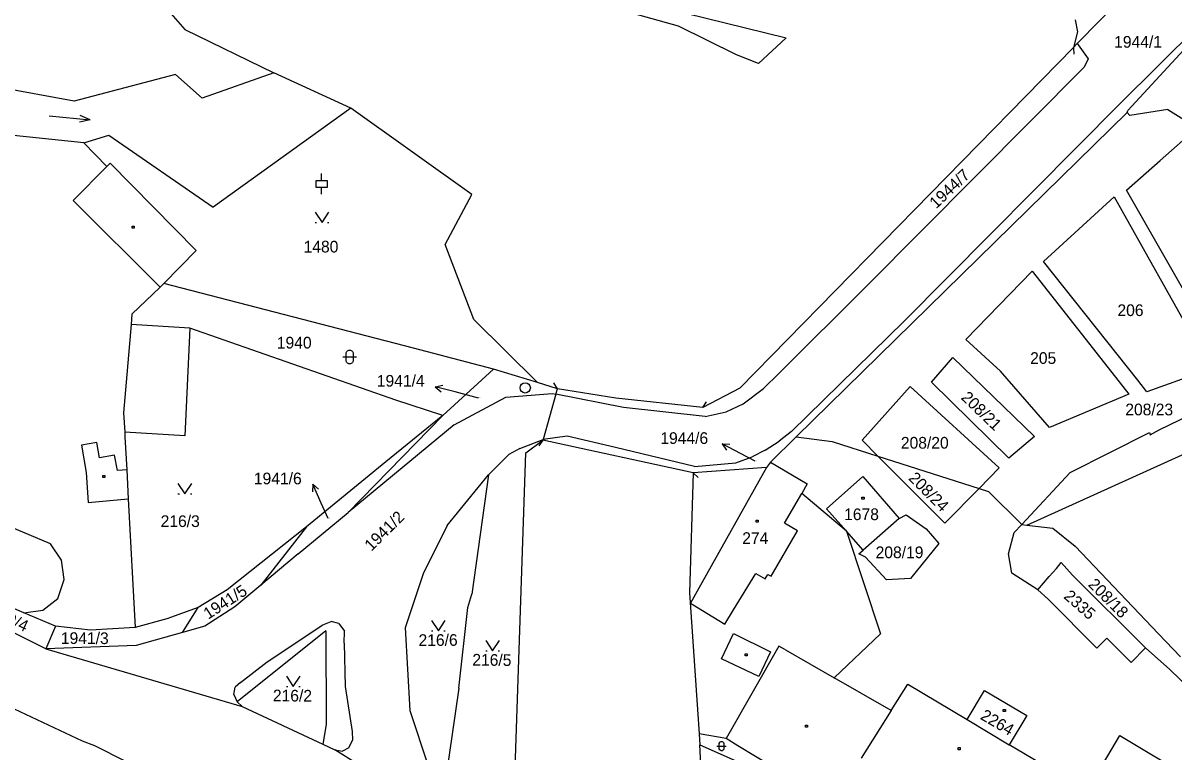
# Model space of a CAD drawing. Extents: x -795483 to -789093, y -1112258 to -1108741.
# Drawn here: x -791907.6 to -791740.2, y -1110894.1 to -1110788.1 of the extents above; entities that cross this region are included whole.
import ezdxf

# ---------------------------------------------------------------- set-up
doc = ezdxf.new("R2010")
doc.units = 0
for name, color, linetype in [('Komunikace', 7, 'Continuous'), ('Popis vodovodních řadů', 7, 'Continuous'), ('Vrstva 1', 7, 'Continuous'), ('Vrstva 14', 7, 'Continuous'), ('Vrstva 15', 7, 'Continuous'), ('Vrstva 16', 7, 'Continuous'), ('Vrstva 2', 7, 'Continuous'), ('Vrstva 23', 7, 'Continuous'), ('Vrstva 25', 7, 'Continuous'), ('Vrstva 28', 7, 'Continuous')]:
    doc.layers.add(name, color=color, linetype=linetype)

msp = doc.modelspace()

# ---------------------------------------------------------------- linework, layer by layer
at = {"layer": 'Komunikace'}
for p, q in [((-791841.35, -1110842.63), (-791844.74, -1110841.73)), ((-791801.13, -1110851.81), (-791803.27, -1110850.69)), ((-791863.23, -1110860.11), (-791864.23, -1110857.89))]:
    msp.add_line(p, q, dxfattribs=at)
at = {"layer": 'Popis vodovodních řadů'}
for p, q in [((-791754.82, -1110791.63), (-791754.78, -1110792.62)), ((-791829.89, -1110841.26), (-791830.39, -1110840.41)), ((-791808.75, -1110843.97), (-791808.2, -1110843.15)), ((-791832, -1110848.76), (-791832.56, -1110849.57)), ((-791810.14, -1110853.5), (-791809.42, -1110854.18))]:
    msp.add_line(p, q, dxfattribs=at)
at = {"layer": 'Vrstva 1'}
for p, q in [((-791894.38, -1110777.13), (-791884.07, -1110789.01)), ((-791812.29, -1110788.52), (-791844.01, -1110779.66)), ((-791746.48, -1110783.12), (-791754.27, -1110791.07)), ((-791814.17, -1110785.93), (-791796.61, -1110790.22)), ((-791803.83, -1110792.73), (-791812.29, -1110788.52)), ((-791754.6, -1110787.64), (-791754.26, -1110789.34)), ((-791736.77, -1110788.62), (-791748.11, -1110799.81)), ((-791884.07, -1110789.01), (-791871.1, -1110795.31)), ((-791796.61, -1110790.22), (-791800.63, -1110793.96)), ((-791754.26, -1110789.34), (-791754.82, -1110791.63)), ((-791736.2, -1110789.15), (-791746.92, -1110800.79)), ((-791803.36, -1110841.2), (-791754.82, -1110791.63)), ((-791754.27, -1110791.07), (-791754.82, -1110791.63)), ((-791754.27, -1110791.07), (-791754.16, -1110791.23)), ((-791754.16, -1110791.23), (-791752.67, -1110793.3)), ((-791800.63, -1110793.96), (-791803.83, -1110792.73)), ((-791752.67, -1110793.3), (-791753.29, -1110794.5)), ((-791871.1, -1110795.31), (-791881.53, -1110798.99)), ((-791859.93, -1110800.45), (-791871.1, -1110795.31)), ((-791753.29, -1110794.5), (-791784.85, -1110826.24)), ((-791900.14, -1110799.45), (-791917.76, -1110796.23)), ((-791885.41, -1110795.57), (-791900.14, -1110799.45)), ((-791881.53, -1110798.99), (-791885.41, -1110795.57)), ((-791779.43, -1110831.43), (-791748.11, -1110799.81)), ((-791859.93, -1110800.45), (-791879.96, -1110814.85)), ((-791842.32, -1110813.02), (-791859.93, -1110800.45)), ((-791795.15, -1110848.25), (-791747.03, -1110801.1)), ((-791747.03, -1110801.1), (-791746.92, -1110800.79)), ((-791746.61, -1110801.53), (-791747.03, -1110801.1)), ((-791741.11, -1110800.67), (-791746.61, -1110801.53)), ((-791741.11, -1110800.67), (-791736.82, -1110803.3)), ((-791742.21, -1110808.05), (-791736.82, -1110803.3)), ((-791898.73, -1110805.48), (-791911.39, -1110804.2)), ((-791898.73, -1110805.48), (-791895.11, -1110804.41)), ((-791895.11, -1110804.41), (-791879.96, -1110814.85)), ((-791895.41, -1110808.96), (-791898.73, -1110805.48)), ((-791894.93, -1110808.48), (-791895.41, -1110808.96)), ((-791882.39, -1110821.16), (-791894.93, -1110808.48)), ((-791747.14, -1110812.4), (-791742.21, -1110808.05)), ((-791846.18, -1110820.3), (-791842.32, -1110813.02)), ((-791759.17, -1110822.74), (-791748.93, -1110813.36)), ((-791748.93, -1110813.36), (-791736.01, -1110836.4)), ((-791733.92, -1110835.51), (-791747.14, -1110812.4)), ((-791842.01, -1110831.17), (-791846.18, -1110820.3)), ((-791887.14, -1110825.95), (-791882.39, -1110821.16)), ((-791745.49, -1110840), (-791759.17, -1110822.74)), ((-791770.5, -1110834.09), (-791760.84, -1110824.16)), ((-791760.84, -1110824.16), (-791747.66, -1110840.95)), ((-791887.66, -1110826.48), (-791891.77, -1110830.43)), ((-791887.14, -1110825.95), (-791887.66, -1110826.48)), ((-791850.81, -1110835.35), (-791887.14, -1110825.95)), ((-791784.85, -1110826.24), (-791797.61, -1110838.98)), ((-791891.77, -1110830.43), (-791891.89, -1110831.92)), ((-791891.89, -1110831.92), (-791892.96, -1110844.76)), ((-791883.33, -1110832.43), (-791891.89, -1110831.92)), ((-791832.79, -1110840.36), (-791842.01, -1110831.17)), ((-791779.43, -1110831.43), (-791795.84, -1110847.47)), ((-791853.37, -1110842.93), (-791883.33, -1110832.43)), ((-791839.15, -1110838.41), (-791850.81, -1110835.35)), ((-791770.5, -1110834.09), (-791765.43, -1110838.69)), ((-791775.47, -1110840.31), (-791772.39, -1110836.7)), ((-791772.39, -1110836.7), (-791760.48, -1110848.22)), ((-791839.15, -1110838.41), (-791846.52, -1110845.16)), ((-791832.79, -1110840.36), (-791839.15, -1110838.41)), ((-791758.33, -1110846.89), (-791765.43, -1110838.69)), ((-791734.89, -1110838.4), (-791744.14, -1110841.69)), ((-791829.89, -1110841.26), (-791832.79, -1110840.36)), ((-791799.91, -1110841.24), (-791797.61, -1110838.98)), ((-791764.23, -1110851.35), (-791775.47, -1110840.31)), ((-791761.62, -1110861.08), (-791714.24, -1110839.64)), ((-791744.14, -1110841.69), (-791745.49, -1110840)), ((-791837.38, -1110842.51), (-791830.66, -1110841.96)), ((-791830.12, -1110842.07), (-791831.97, -1110848.65)), ((-791830.66, -1110841.96), (-791830.12, -1110842.07)), ((-791830.12, -1110842.07), (-791829.89, -1110841.26)), ((-791820.27, -1110843.98), (-791830.12, -1110842.07)), ((-791821.37, -1110842.61), (-791829.89, -1110841.26)), ((-791803.36, -1110841.2), (-791808.75, -1110843.97)), ((-791802.88, -1110843.44), (-791799.91, -1110841.24)), ((-791785.57, -1110848.76), (-791778.6, -1110840.95)), ((-791778.6, -1110840.95), (-791765.62, -1110852.78)), ((-791746.8, -1110842.05), (-791758.33, -1110846.89)), ((-791747.66, -1110840.95), (-791746.8, -1110842.05)), ((-791846.52, -1110845.16), (-791853.37, -1110842.93)), ((-791844.89, -1110846.53), (-791837.38, -1110842.51)), ((-791808.75, -1110843.97), (-791821.37, -1110842.61)), ((-791805.32, -1110844.61), (-791802.88, -1110843.44)), ((-791742.35, -1110847.24), (-791732.22, -1110842.34)), ((-791892.96, -1110844.76), (-791892.81, -1110847.56)), ((-791860.31, -1110859.26), (-791846.52, -1110845.16)), ((-791846.52, -1110845.16), (-791854.85, -1110851.89)), ((-791808.39, -1110845.32), (-791820.27, -1110843.98)), ((-791808.39, -1110845.32), (-791805.32, -1110844.61)), ((-791844.89, -1110846.53), (-791860.31, -1110859.26)), ((-791892.81, -1110847.56), (-791892.77, -1110848.26)), ((-791892.77, -1110848.26), (-791892.51, -1110853.06)), ((-791835.35, -1110849.94), (-791831.97, -1110848.65)), ((-791834.48, -1110850.6), (-791832, -1110848.76)), ((-791832, -1110848.76), (-791831.97, -1110848.65)), ((-791810.14, -1110853.5), (-791832, -1110848.76)), ((-791828.44, -1110848.15), (-791831.97, -1110848.65)), ((-791821.41, -1110849.79), (-791828.44, -1110848.15)), ((-791799.66, -1110850.18), (-791797.61, -1110848.87)), ((-791798.91, -1110851.94), (-791795.15, -1110848.25)), ((-791795.84, -1110847.47), (-791797.61, -1110848.87)), ((-791795.15, -1110848.25), (-791789.91, -1110848.95)), ((-791785.57, -1110848.76), (-791783.27, -1110851.07)), ((-791760.48, -1110848.22), (-791764.23, -1110851.35)), ((-791755.33, -1110853.44), (-791743.79, -1110847.64)), ((-791743.79, -1110847.64), (-791743.67, -1110847.95)), ((-791743.67, -1110847.95), (-791742.35, -1110847.24)), ((-791835.35, -1110849.94), (-791836.94, -1110850.83)), ((-791809.96, -1110852.58), (-791821.41, -1110849.79)), ((-791799.66, -1110850.18), (-791801.56, -1110851.15)), ((-791789.91, -1110848.95), (-791783.27, -1110851.07)), ((-791854.85, -1110851.89), (-791866.37, -1110861.35)), ((-791836.94, -1110850.83), (-791839.92, -1110853.77)), ((-791836.18, -1110901.7), (-791834.48, -1110850.6)), ((-791809.96, -1110852.58), (-791803.92, -1110852.02)), ((-791803.92, -1110852.02), (-791801.56, -1110851.15)), ((-791798.91, -1110851.94), (-791799.46, -1110852.71)), ((-791798.91, -1110851.94), (-791793.54, -1110855.1)), ((-791773.53, -1110860.81), (-791783.27, -1110851.07)), ((-791783.27, -1110851.07), (-791768.55, -1110855.76)), ((-791892.51, -1110853.06), (-791892.29, -1110857.28)), ((-791845.91, -1110861.16), (-791839.92, -1110853.77)), ((-791839.92, -1110853.77), (-791842.33, -1110871.11)), ((-791810.14, -1110853.5), (-791810.69, -1110870.94)), ((-791799.46, -1110852.71), (-791810.14, -1110853.5)), ((-791765.62, -1110852.78), (-791768.55, -1110855.76)), ((-791762.35, -1110860.99), (-791755.33, -1110853.44)), ((-791793.54, -1110855.1), (-791794.34, -1110856.5)), ((-791790.74, -1110858.73), (-791785.47, -1110854.03)), ((-791785.47, -1110854.03), (-791780.16, -1110860.15)), ((-791787.85, -1110861.97), (-791794.34, -1110856.5)), ((-791773.53, -1110860.81), (-791768.55, -1110855.76)), ((-791768.55, -1110855.76), (-791767.2, -1110856.19)), ((-791767.2, -1110856.19), (-791762.35, -1110860.99)), ((-791892.29, -1110857.28), (-791891.28, -1110876)), ((-791787.85, -1110861.97), (-791790.74, -1110858.73)), ((-791907.46, -1110873.84), (-791939.94, -1110860.09)), ((-791867.6, -1110865.28), (-791860.31, -1110859.26)), ((-791780.16, -1110860.15), (-791785.4, -1110864.72)), ((-791780.16, -1110860.15), (-791779.18, -1110859.58)), ((-791779.18, -1110859.58), (-791776.26, -1110861.61)), ((-791866.37, -1110861.35), (-791877.91, -1110870.49)), ((-791866.37, -1110861.35), (-791872.99, -1110869.81)), ((-791845.91, -1110861.16), (-791849.39, -1110868.16)), ((-791787.85, -1110861.97), (-791782.9, -1110876.92)), ((-791785.4, -1110864.72), (-791787.85, -1110861.97)), ((-791776.26, -1110861.61), (-791774.41, -1110863.75)), ((-791764.26, -1110865.28), (-791763.43, -1110862.15)), ((-791763.43, -1110862.15), (-791762.35, -1110860.99)), ((-791762.35, -1110860.99), (-791761.62, -1110861.08)), ((-791761.62, -1110861.08), (-791757.81, -1110861.54)), ((-791757.81, -1110861.54), (-791754.58, -1110864.14)), ((-791774.41, -1110863.75), (-791778.51, -1110868.84)), ((-791867.6, -1110865.28), (-791872.99, -1110869.81)), ((-791786.03, -1110865.27), (-791785.4, -1110864.72)), ((-791785.05, -1110865.75), (-791786.03, -1110865.27)), ((-791763.77, -1110868.09), (-791764.26, -1110865.28)), ((-791754.58, -1110864.14), (-791742.48, -1110876.91)), ((-791782.03, -1110869.05), (-791785.05, -1110865.75)), ((-791757.32, -1110867.39), (-791756.61, -1110866.53)), ((-791756.61, -1110866.53), (-791754.97, -1110868.38)), ((-791849.39, -1110868.16), (-791852.01, -1110876.03)), ((-791778.51, -1110868.84), (-791782.03, -1110869.05)), ((-791760, -1110870.51), (-791763.77, -1110868.09)), ((-791760, -1110870.51), (-791758.34, -1110868.57)), ((-791758.34, -1110868.57), (-791757.32, -1110867.39)), ((-791744.33, -1110878.96), (-791754.97, -1110868.38)), ((-791877.91, -1110870.49), (-791882.12, -1110873.06)), ((-791872.99, -1110869.81), (-791876.77, -1110872.98)), ((-791758.53, -1110871.87), (-791760, -1110870.51)), ((-791842.9, -1110873.09), (-791842.33, -1110871.11)), ((-791810.69, -1110870.94), (-791809.26, -1110891.45)), ((-791751.45, -1110879), (-791758.53, -1110871.87)), ((-791902.87, -1110875.81), (-791907.46, -1110873.84)), ((-791882.12, -1110873.06), (-791886.7, -1110874.73)), ((-791884.4, -1110876.7), (-791882.12, -1110873.06)), ((-791876.77, -1110872.98), (-791881.13, -1110875.77)), ((-791844.2, -1110884.82), (-791842.9, -1110873.09)), ((-791886.7, -1110874.73), (-791891.28, -1110876)), ((-791898.93, -1110892.51), (-791934.57, -1110875.82)), ((-791904.28, -1110879.09), (-791908.73, -1110876.84)), ((-791902.87, -1110875.81), (-791904.28, -1110879.09)), ((-791897.79, -1110876.36), (-791902.87, -1110875.81)), ((-791891.28, -1110876), (-791897.79, -1110876.36)), ((-791884.4, -1110876.7), (-791891.14, -1110878.62)), ((-791881.13, -1110875.77), (-791884.4, -1110876.7)), ((-791863.57, -1110876.49), (-791876.47, -1110886.81)), ((-791863.57, -1110876.49), (-791863.52, -1110890.07)), ((-791852.01, -1110876.03), (-791851.35, -1110888.05)), ((-791782.9, -1110876.92), (-791789.61, -1110883.31)), ((-791742.48, -1110876.91), (-791739.28, -1110880.24)), ((-791891.14, -1110878.62), (-791904.28, -1110879.09)), ((-791797.68, -1110878.7), (-791805.34, -1110892.14)), ((-791796.71, -1110879.25), (-791797.68, -1110878.7)), ((-791750, -1110877.55), (-791751.45, -1110879)), ((-791746.45, -1110881.09), (-791750, -1110877.55)), ((-791744.33, -1110878.96), (-791746.45, -1110881.09)), ((-791740.83, -1110882.08), (-791744.33, -1110878.96)), ((-791904.28, -1110879.09), (-791875.7, -1110887.48)), ((-791796.71, -1110879.25), (-791789.61, -1110883.31)), ((-791730.17, -1110892.47), (-791740.83, -1110882.08)), ((-791781.33, -1110888.04), (-791789.61, -1110883.31)), ((-791844.2, -1110884.82), (-791846.39, -1110899.61)), ((-791781.33, -1110888.04), (-791778.93, -1110884.24)), ((-791778.93, -1110884.24), (-791770.29, -1110889.37)), ((-791770.29, -1110889.37), (-791767.78, -1110885.14)), ((-791767.78, -1110885.14), (-791761.63, -1110888.77)), ((-791875.7, -1110887.48), (-791876.47, -1110886.81)), ((-791875.7, -1110887.48), (-791864, -1110892.94)), ((-791851.35, -1110888.05), (-791848.69, -1110896.1)), ((-791761.63, -1110888.77), (-791764.16, -1110893.02)), ((-791863.52, -1110890.07), (-791864, -1110892.94)), ((-791770.29, -1110889.37), (-791764.16, -1110893.02)), ((-791805.34, -1110892.14), (-791809.26, -1110891.45)), ((-791809.26, -1110891.45), (-791809.18, -1110893.03)), ((-791803.63, -1110893.17), (-791805.34, -1110892.14)), ((-791753.02, -1110899.97), (-791748.09, -1110891.69)), ((-791748.09, -1110891.69), (-791718.22, -1110909.47)), ((-791897.16, -1110893.17), (-791898.93, -1110892.51)), ((-791892.66, -1110895.47), (-791897.16, -1110893.17)), ((-791864, -1110892.94), (-791862.24, -1110893.76)), ((-791839.67, -1110907.9), (-791862.24, -1110893.76)), ((-791809.18, -1110893.03), (-791789.18, -1110901.88)), ((-791808.61, -1110904.53), (-791809.18, -1110893.03)), ((-791789.18, -1110901.88), (-791803.63, -1110893.17)), ((-791756.21, -1110897.75), (-791764.16, -1110893.02))]:
    msp.add_line(p, q, dxfattribs=at)
at = {"layer": 'Vrstva 16'}
for p, q in [((-791847.64, -1110840.96), (-791846.54, -1110840.73)), ((-791844.74, -1110841.73), (-791847.64, -1110840.96)), ((-791847.64, -1110840.96), (-791846.8, -1110841.7)), ((-791803.27, -1110850.69), (-791805.93, -1110849.29)), ((-791805.93, -1110849.29), (-791805.27, -1110850.2)), ((-791805.93, -1110849.29), (-791804.81, -1110849.32)), ((-791865.47, -1110855.16), (-791865.51, -1110856.27)), ((-791864.23, -1110857.89), (-791865.47, -1110855.16)), ((-791865.47, -1110855.16), (-791864.6, -1110855.86))]:
    msp.add_line(p, q, dxfattribs=at)
at = {"layer": 'Vrstva 2'}
for p, q in [((-791895.41, -1110808.96), (-791900.29, -1110813.87)), ((-791900.29, -1110813.87), (-791887.66, -1110826.48)), ((-791883.33, -1110832.43), (-791884.06, -1110848.13)), ((-791884.06, -1110848.13), (-791892.81, -1110847.56)), ((-791896.88, -1110849.07), (-791899.08, -1110849.47)), ((-791899.08, -1110849.47), (-791898.42, -1110853.44)), ((-791896.47, -1110851.31), (-791896.88, -1110849.07)), ((-791894.28, -1110850.91), (-791896.47, -1110851.31)), ((-791893.86, -1110853.13), (-791894.28, -1110850.91)), ((-791898.42, -1110853.44), (-791898.1, -1110857.79)), ((-791892.51, -1110853.06), (-791893.86, -1110853.13)), ((-791799.46, -1110852.71), (-791809.33, -1110870.27)), ((-791903.61, -1110863.83), (-791924.1, -1110855.18)), ((-791796.83, -1110860.82), (-791794.34, -1110856.5)), ((-791898.1, -1110857.79), (-791892.29, -1110857.28)), ((-791798.81, -1110868.53), (-791794.97, -1110861.9)), ((-791794.97, -1110861.9), (-791796.83, -1110860.82)), ((-791902.02, -1110866.18), (-791903.61, -1110863.83)), ((-791901.61, -1110868.99), (-791902.02, -1110866.18)), ((-791804.25, -1110873.41), (-791801.03, -1110868.12)), ((-791801.03, -1110868.12), (-791799.66, -1110868.92)), ((-791799.66, -1110868.92), (-791799.28, -1110868.26)), ((-791799.28, -1110868.26), (-791798.81, -1110868.53)), ((-791902.55, -1110871.74), (-791901.61, -1110868.99)), ((-791809.33, -1110870.27), (-791810.53, -1110872.42)), ((-791904.7, -1110873.47), (-791902.55, -1110871.74)), ((-791907.46, -1110873.84), (-791904.7, -1110873.47)), ((-791810.53, -1110872.42), (-791805.53, -1110875.51)), ((-791805.53, -1110875.51), (-791804.25, -1110873.41)), ((-791872.09, -1110880.95), (-791864, -1110875.58)), ((-791864, -1110875.58), (-791862.8, -1110875.1)), ((-791861.66, -1110875.41), (-791862.8, -1110875.1)), ((-791861.66, -1110875.41), (-791860.83, -1110876.52)), ((-791860.89, -1110878.24), (-791860.83, -1110876.52)), ((-791806, -1110880.53), (-791804.28, -1110876.86)), ((-791804.28, -1110876.86), (-791798.9, -1110879.51)), ((-791860.89, -1110878.24), (-791860.74, -1110884.58)), ((-791800.61, -1110883.1), (-791806, -1110880.53)), ((-791798.9, -1110879.51), (-791800.61, -1110883.1)), ((-791875.98, -1110883.97), (-791872.09, -1110880.95)), ((-791875.98, -1110883.97), (-791876.73, -1110884.66)), ((-791876.93, -1110885.74), (-791876.73, -1110884.66)), ((-791860.74, -1110884.58), (-791859.72, -1110891.11)), ((-791876.93, -1110885.74), (-791876.47, -1110886.81)), ((-791781.33, -1110888.04), (-791785.71, -1110895)), ((-791860.2, -1110893.49), (-791859.67, -1110892.38)), ((-791859.72, -1110891.11), (-791859.67, -1110892.38)), ((-791862.24, -1110893.76), (-791861.12, -1110893.94)), ((-791860.2, -1110893.49), (-791861.12, -1110893.94))]:
    msp.add_line(p, q, dxfattribs=at)
at = {"layer": 'Vrstva 23'}
for p, q in [((-791903.81, -1110801.6), (-791897.83, -1110802.14)), ((-791897.83, -1110802.14), (-791899.28, -1110801.51)), ((-791897.83, -1110802.14), (-791899.37, -1110802.5)), ((-791864.18, -1110810.98), (-791864.18, -1110809.98)), ((-791864.98, -1110811.98), (-791864.98, -1110810.98)), ((-791864.98, -1110810.98), (-791863.38, -1110810.98)), ((-791863.38, -1110811.98), (-791864.98, -1110811.98)), ((-791864.18, -1110812.98), (-791864.18, -1110811.98)), ((-791863.38, -1110810.98), (-791863.38, -1110811.98)), ((-791865.11, -1110815.58), (-791864.11, -1110817.08)), ((-791865.11, -1110817.08), (-791864.91, -1110817.08)), ((-791864.11, -1110817.08), (-791863.11, -1110815.58)), ((-791863.31, -1110817.08), (-791863.11, -1110817.08)), ((-791861.09, -1110836.63), (-791859.09, -1110836.63)), ((-791860.59, -1110836.03), (-791860.49, -1110835.83)), ((-791860.59, -1110837.23), (-791860.59, -1110836.03)), ((-791860.49, -1110835.83), (-791860.39, -1110835.73)), ((-791860.39, -1110835.73), (-791860.19, -1110835.63)), ((-791860.19, -1110835.63), (-791859.99, -1110835.63)), ((-791859.99, -1110835.63), (-791859.79, -1110835.73)), ((-791859.79, -1110835.73), (-791859.69, -1110835.83)), ((-791859.69, -1110835.83), (-791859.59, -1110836.03)), ((-791859.59, -1110836.03), (-791859.59, -1110837.23)), ((-791860.49, -1110837.43), (-791860.59, -1110837.23)), ((-791860.39, -1110837.53), (-791860.49, -1110837.43)), ((-791860.19, -1110837.63), (-791860.39, -1110837.53)), ((-791859.99, -1110837.63), (-791860.19, -1110837.63)), ((-791859.79, -1110837.53), (-791859.99, -1110837.63)), ((-791859.69, -1110837.43), (-791859.79, -1110837.53)), ((-791859.59, -1110837.23), (-791859.69, -1110837.43)), ((-791885.06, -1110855.03), (-791884.06, -1110856.53)), ((-791884.06, -1110856.53), (-791883.06, -1110855.03)), ((-791885.06, -1110856.53), (-791884.86, -1110856.53)), ((-791883.26, -1110856.53), (-791883.06, -1110856.53)), ((-791848.19, -1110874.96), (-791847.19, -1110876.46)), ((-791847.19, -1110876.46), (-791846.19, -1110874.96)), ((-791848.19, -1110876.46), (-791847.99, -1110876.46)), ((-791846.39, -1110876.46), (-791846.19, -1110876.46)), ((-791840.31, -1110877.85), (-791839.31, -1110879.35)), ((-791839.31, -1110879.35), (-791838.31, -1110877.85)), ((-791840.31, -1110879.35), (-791840.11, -1110879.35)), ((-791838.51, -1110879.35), (-791838.31, -1110879.35)), ((-791869.29, -1110883.04), (-791868.29, -1110884.54)), ((-791868.29, -1110884.54), (-791867.29, -1110883.04)), ((-791869.29, -1110884.54), (-791869.09, -1110884.54)), ((-791867.49, -1110884.54), (-791867.29, -1110884.54)), ((-791806.68, -1110893.23), (-791805.34, -1110893.23)), ((-791806.34, -1110892.83), (-791806.28, -1110892.69)), ((-791806.34, -1110893.63), (-791806.34, -1110892.83)), ((-791806.28, -1110893.77), (-791806.34, -1110893.63)), ((-791806.28, -1110892.69), (-791806.21, -1110892.63)), ((-791806.21, -1110893.83), (-791806.28, -1110893.77)), ((-791806.21, -1110892.63), (-791806.08, -1110892.56)), ((-791806.08, -1110893.9), (-791806.21, -1110893.83)), ((-791806.08, -1110892.56), (-791805.94, -1110892.56)), ((-791805.94, -1110893.9), (-791806.08, -1110893.9)), ((-791805.94, -1110892.56), (-791805.81, -1110892.63)), ((-791805.81, -1110893.83), (-791805.94, -1110893.9)), ((-791805.81, -1110892.63), (-791805.74, -1110892.69)), ((-791805.74, -1110893.77), (-791805.81, -1110893.83)), ((-791805.74, -1110892.69), (-791805.68, -1110892.83)), ((-791805.68, -1110893.63), (-791805.74, -1110893.77)), ((-791805.68, -1110892.83), (-791805.68, -1110893.63))]:
    msp.add_line(p, q, dxfattribs=at)
at = {"layer": 'Vrstva 25'}
for p, q in [((-791891.73, -1110817.61), (-791891.43, -1110817.61)), ((-791891.73, -1110817.91), (-791891.73, -1110817.61)), ((-791891.43, -1110817.91), (-791891.73, -1110817.91)), ((-791891.43, -1110817.61), (-791891.43, -1110817.91)), ((-791895.98, -1110853.87), (-791895.68, -1110853.87)), ((-791895.98, -1110854.17), (-791895.98, -1110853.87)), ((-791895.68, -1110853.87), (-791895.68, -1110854.17)), ((-791895.68, -1110854.17), (-791895.98, -1110854.17)), ((-791785.59, -1110857.03), (-791785.29, -1110857.03)), ((-791785.59, -1110857.33), (-791785.59, -1110857.03)), ((-791785.29, -1110857.03), (-791785.29, -1110857.33)), ((-791785.29, -1110857.33), (-791785.59, -1110857.33)), ((-791800.99, -1110860.38), (-791800.69, -1110860.38)), ((-791800.99, -1110860.68), (-791800.99, -1110860.38)), ((-791800.69, -1110860.38), (-791800.69, -1110860.68)), ((-791800.69, -1110860.68), (-791800.99, -1110860.68)), ((-791802.59, -1110879.82), (-791802.29, -1110879.82)), ((-791802.59, -1110880.12), (-791802.59, -1110879.82)), ((-791802.29, -1110880.12), (-791802.59, -1110880.12)), ((-791802.29, -1110879.82), (-791802.29, -1110880.12)), ((-791765.03, -1110887.89), (-791764.73, -1110887.89)), ((-791765.03, -1110888.19), (-791765.03, -1110887.89)), ((-791764.73, -1110888.19), (-791765.03, -1110888.19)), ((-791764.73, -1110887.89), (-791764.73, -1110888.19)), ((-791793.79, -1110890.17), (-791793.49, -1110890.17)), ((-791793.79, -1110890.47), (-791793.79, -1110890.17)), ((-791793.49, -1110890.47), (-791793.79, -1110890.47)), ((-791793.49, -1110890.17), (-791793.49, -1110890.47)), ((-791771.6, -1110893.45), (-791771.3, -1110893.45)), ((-791771.6, -1110893.75), (-791771.6, -1110893.45)), ((-791771.3, -1110893.75), (-791771.6, -1110893.75)), ((-791771.3, -1110893.45), (-791771.3, -1110893.75))]:
    msp.add_line(p, q, dxfattribs=at)
at = {"layer": 'Vrstva 28'}
for radius in [0.75, 0.01]:
    msp.add_circle((-791834.56, -1110841.14), radius, dxfattribs=at)

# ---------------------------------------------------------------- texts
at = {"layer": 'Vrstva 14'}
for s, height, p in [('1944/1', 1.7, (-791748.91, -1110791.67)), ('1480', 1.7, (-791866.79, -1110821.45)), ('206', 1.7, (-791748.43, -1110830.69)), ('1940', 1.7, (-791870.68, -1110835.41)), ('205', 1.7, (-791761.13, -1110837.65)), ('1941/4', 0.1, (-791841.35, -1110842.63)), ('208/23', 1.7, (-791747.29, -1110845.13)), ('208/20', 1.7, (-791779.93, -1110849.97)), ('1944/6', 0.1, (-791801.13, -1110851.81)), ('216/3', 1.7, (-791887.58, -1110861.37)), ('1941/6', 0.1, (-791863.23, -1110860.11)), ('208/19', 1.7, (-791783.6, -1110865.9))]:
    msp.add_text(s, height=height, dxfattribs=at).set_placement(p)
for s, rotation, p in [('1944/7', 43.3262, (-791774.8, -1110815.18)), ('208/21', 316.019, (-791771.28, -1110842.67)), ('208/24', 315, (-791778.92, -1110854.38)), ('1941/2', 44.6452, (-791856.93, -1110864.97)), ('208/18', 315.1293, (-791752.81, -1110869.85)), ('1941/5', 32.9293, (-791880.66, -1110874.86)), ('2335', 318.7199, (-791756.36, -1110871.62)), ('1939/4', 334.828, (-791913.62, -1110873.71)), ('1941/3', 359.7982, (-791902.09, -1110878.37)), ('216/6', 0.2745, (-791850.07, -1110878.67)), ('216/5', 359.4632, (-791842.26, -1110881.52)), ('216/2', 359.61, (-791871.26, -1110886.72))]:
    msp.add_text(s, height=1.7, rotation=rotation, dxfattribs=at).set_placement(p)
at = {"layer": 'Vrstva 15'}
for s, p in [('1678', (-791788.18, -1110860.37)), ('274', (-791803, -1110863.83))]:
    msp.add_text(s, height=1.7, dxfattribs=at).set_placement(p)
msp.add_text('2264', height=1.7, rotation=329.8392, dxfattribs=at).set_placement((-791768.5, -1110889.23))
at = {"layer": 'Vrstva 16'}
for s, p in [('1941/4', (-791856.14, -1110840.96)), ('1944/6', (-791814.91, -1110849.29)), ('1941/6', (-791874.02, -1110855.16))]:
    msp.add_text(s, height=1.7, dxfattribs=at).set_placement(p)

doc.saveas('drawing.dxf')
